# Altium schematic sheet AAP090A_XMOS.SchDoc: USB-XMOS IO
size 538 x 342 mm; Date: Not shown in title block; ApprovedBy: Not shown in title block; CheckedBy: Not shown in title block; Author: Not shown in title block; CompanyName: Not shown in title block; DrawnBy: LDN; Engineer: Not shown in title block; Organization: Not shown in title block; Address1: Not shown in title block; Address2: Not shown in title block; Address3: Not shown in title block; Address4: Not shown in title block; DocumentNumber: 1; Revision: Use project parameter SCH_Rev; SheetNumber: 1; SheetTotal: 6; PageSetup: Record=PageOptions¦CenterHorizontal=True¦CenterVertical=True¦PrintScale=0.77¦XCorrection=1.00¦YCorrection=1.00¦PrintKind=0¦BorderSize=5000000¦LeftOffset=0¦BottomOffset=0¦Orientation=2¦PaperLength=1000¦PaperWidth=1000¦Scale=100¦PaperSource=15¦PrintQuality=600¦MediaType=1¦DitherType=10¦PrintScaleMode=1¦PaperKind=Tabloid (11 x 17")¦PaperIndex=17
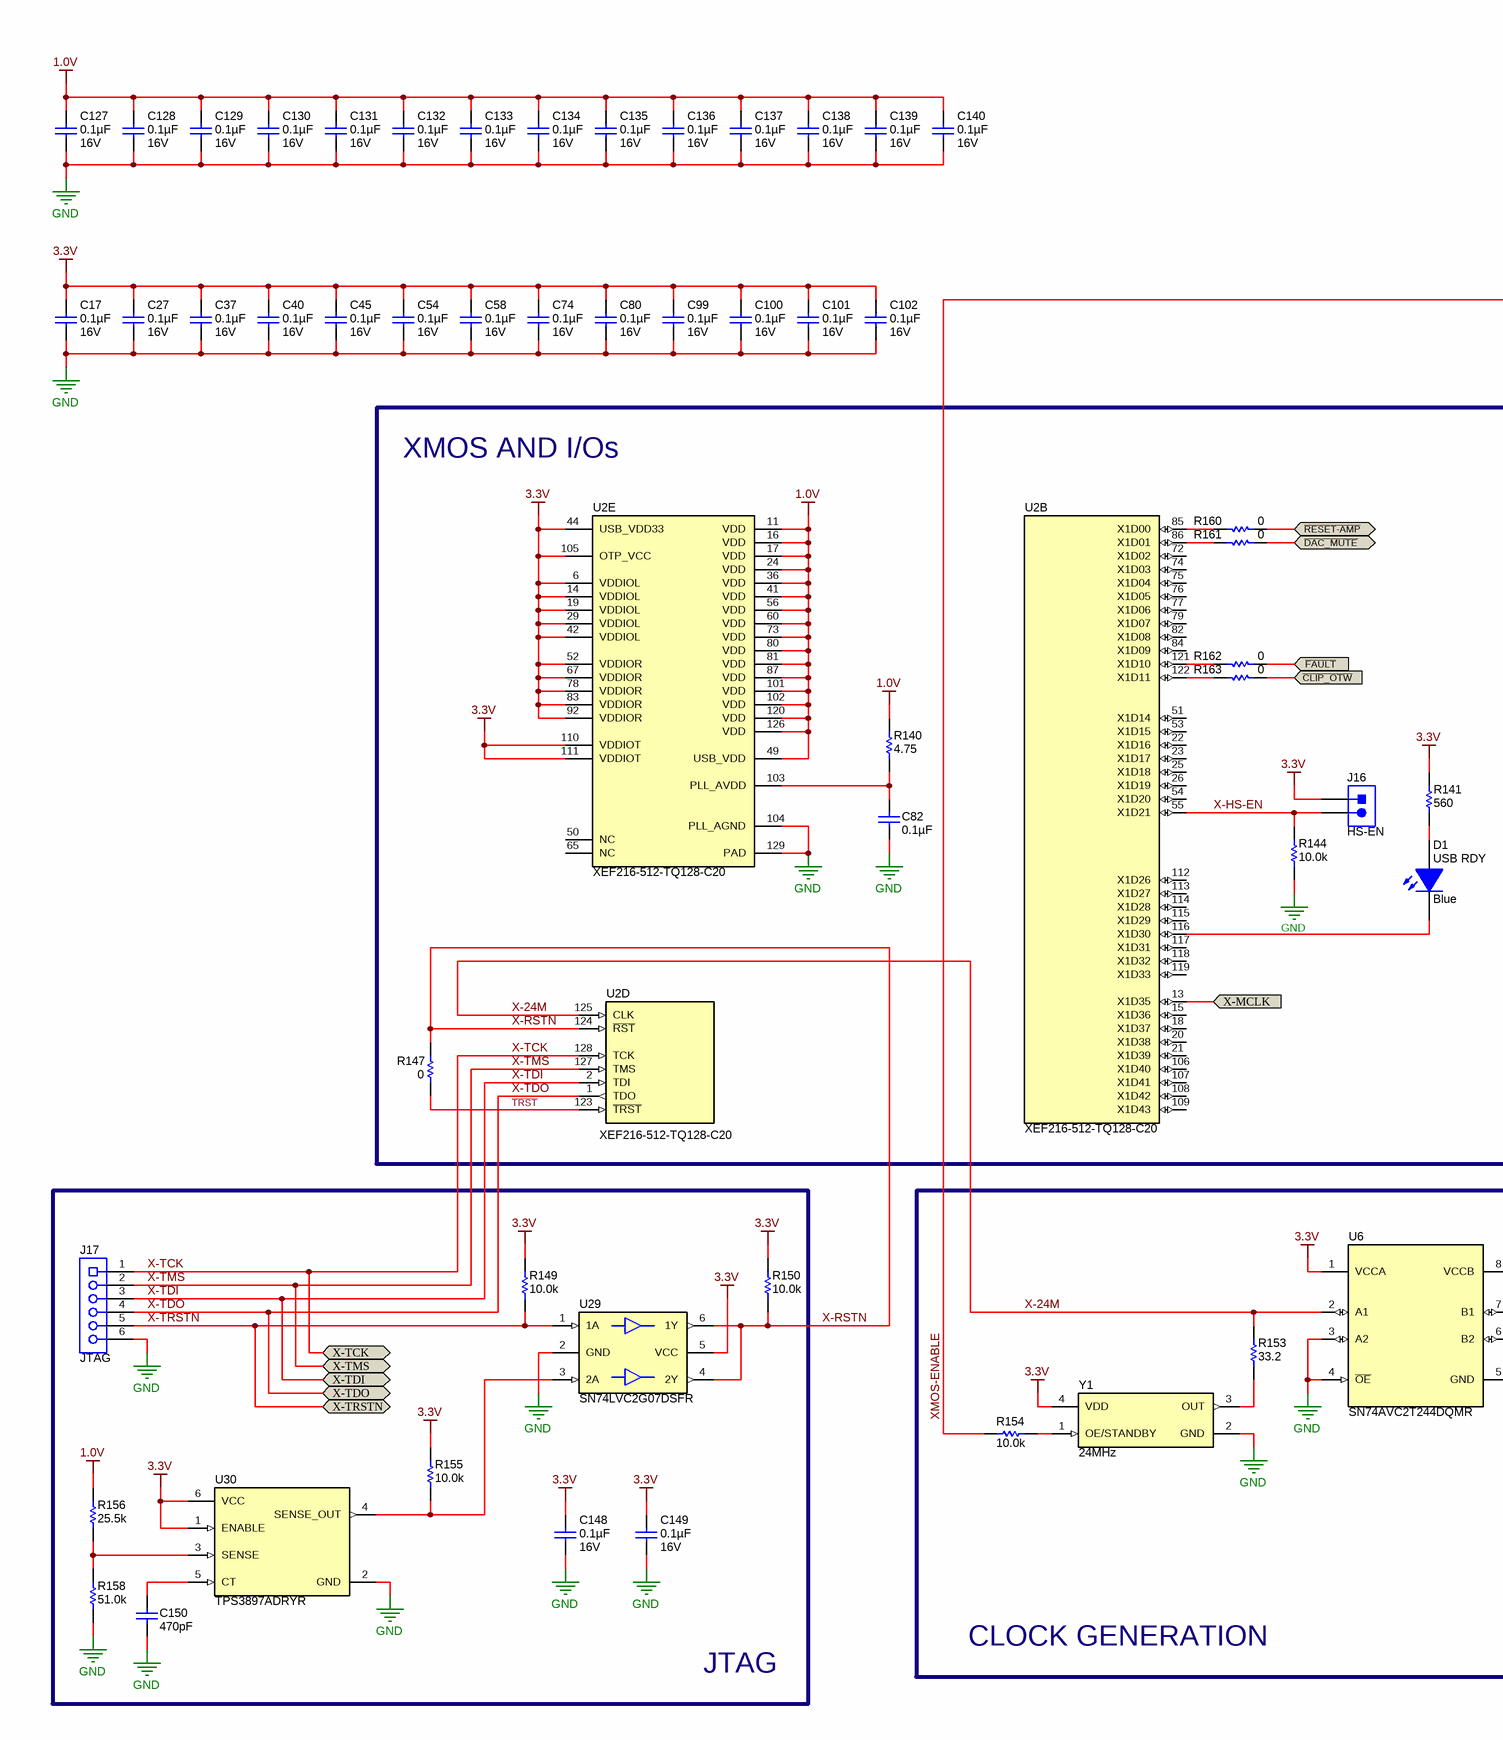
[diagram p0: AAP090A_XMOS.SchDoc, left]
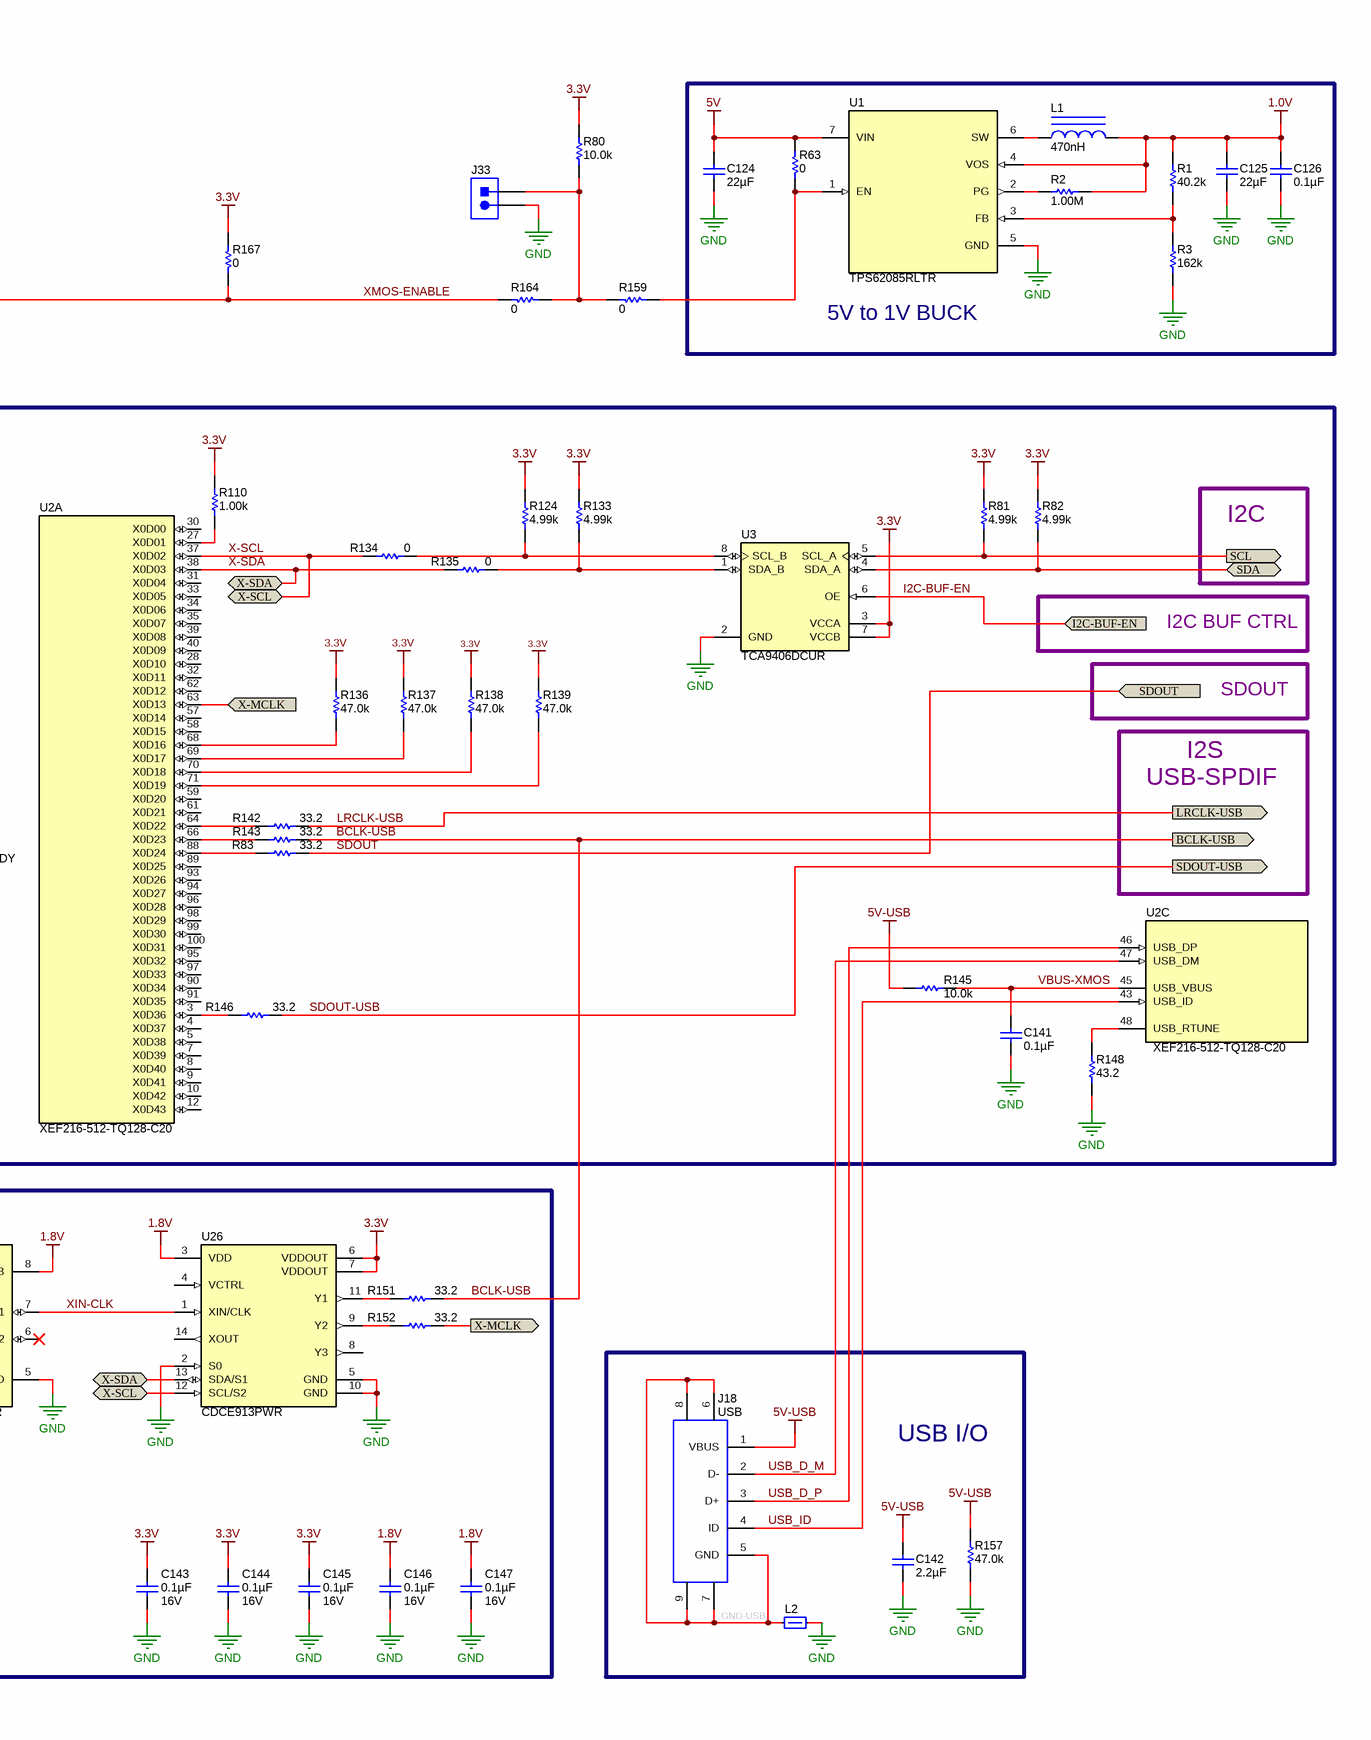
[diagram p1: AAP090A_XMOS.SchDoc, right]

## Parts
(Parts that share a designator on the sheet are numbered #1, #2 ... from top to bottom, then left to right.)
C17  ValueDisplayed: 0.1µF  Value2: 16V  [0402L]  (hidden comment: GRM155R71C104KA88D)
C27  ValueDisplayed: 0.1µF  Value2: 16V  [0402L]  (hidden comment: GRM155R71C104KA88D)
C37  ValueDisplayed: 0.1µF  Value2: 16V  [0402L]  (hidden comment: GRM155R71C104KA88D)
C40  ValueDisplayed: 0.1µF  Value2: 16V  [0402L]  (hidden comment: GRM155R71C104KA88D)
C45  ValueDisplayed: 0.1µF  Value2: 16V  [0402L]  (hidden comment: GRM155R71C104KA88D)
C54  ValueDisplayed: 0.1µF  Value2: 16V  [0402L]  (hidden comment: GRM155R71C104KA88D)
C58  ValueDisplayed: 0.1µF  Value2: 16V  [0402L]  (hidden comment: GRM155R71C104KA88D)
C74  ValueDisplayed: 0.1µF  Value2: 16V  [0402L]  (hidden comment: GRM155R71C104KA88D)
C80  ValueDisplayed: 0.1µF  Value2: 16V  [0402L]  (hidden comment: GRM155R71C104KA88D)
C82  ValueDisplayed: 0.1µF  [0402L]
C99  ValueDisplayed: 0.1µF  Value2: 16V  [0402L]  (hidden comment: GRM155R71C104KA88D)
C100  ValueDisplayed: 0.1µF  Value2: 16V  [0402L]  (hidden comment: GRM155R71C104KA88D)
C101  ValueDisplayed: 0.1µF  Value2: 16V  [0402L]  (hidden comment: GRM155R71C104KA88D)
C102  ValueDisplayed: 0.1µF  Value2: 16V  [0402L]  (hidden comment: GRM155R71C104KA88D)
C124  ValueDisplayed: 22µF  [0805_KTR]  (hidden comment: GRM21BZ71A226ME15L)
C125  ValueDisplayed: 22µF  [0805_KTR]  (hidden comment: GRM21BZ71A226ME15L)
C126  ValueDisplayed: 0.1µF  [0402L]  (hidden comment: GRM155R71C104KA88D)
C127  ValueDisplayed: 0.1µF  Value2: 16V  [0402L]  (hidden comment: GRM155R71C104KA88D)
C128  ValueDisplayed: 0.1µF  Value2: 16V  [0402L]  (hidden comment: GRM155R71C104KA88D)
C129  ValueDisplayed: 0.1µF  Value2: 16V  [0402L]  (hidden comment: GRM155R71C104KA88D)
C130  ValueDisplayed: 0.1µF  Value2: 16V  [0402L]  (hidden comment: GRM155R71C104KA88D)
C131  ValueDisplayed: 0.1µF  Value2: 16V  [0402L]  (hidden comment: GRM155R71C104KA88D)
C132  ValueDisplayed: 0.1µF  Value2: 16V  [0402L]  (hidden comment: GRM155R71C104KA88D)
C133  ValueDisplayed: 0.1µF  Value2: 16V  [0402L]  (hidden comment: GRM155R71C104KA88D)
C134  ValueDisplayed: 0.1µF  Value2: 16V  [0402L]  (hidden comment: GRM155R71C104KA88D)
C135  ValueDisplayed: 0.1µF  Value2: 16V  [0402L]  (hidden comment: GRM155R71C104KA88D)
C136  ValueDisplayed: 0.1µF  Value2: 16V  [0402L]  (hidden comment: GRM155R71C104KA88D)
C137  ValueDisplayed: 0.1µF  Value2: 16V  [0402L]  (hidden comment: GRM155R71C104KA88D)
C138  ValueDisplayed: 0.1µF  Value2: 16V  [0402L]  (hidden comment: GRM155R71C104KA88D)
C139  ValueDisplayed: 0.1µF  Value2: 16V  [0402L]  (hidden comment: GRM155R71C104KA88D)
C140  ValueDisplayed: 0.1µF  Value2: 16V  [0402L]  (hidden comment: GRM155R71C104KA88D)
C141  ValueDisplayed: 0.1µF  [0402L]  (hidden comment: GRM155R71C104KA88D)
C142  ValueDisplayed: 2.2µF  [0603L]  (hidden comment: GRM188R71A225KE15D)
C143  ValueDisplayed: 0.1µF  Value2: 16V  [0402L]  (hidden comment: GRM155R71C104KA88D)
C144  ValueDisplayed: 0.1µF  Value2: 16V  [0402L]  (hidden comment: GRM155R71C104KA88D)
C145  ValueDisplayed: 0.1µF  Value2: 16V  [0402L]  (hidden comment: GRM155R71C104KA88D)
C146  ValueDisplayed: 0.1µF  Value2: 16V  [0402L]  (hidden comment: GRM155R71C104KA88D)
C147  ValueDisplayed: 0.1µF  Value2: 16V  [0402L]  (hidden comment: GRM155R71C104KA88D)
C148  ValueDisplayed: 0.1µF  Value2: 16V  [0402L]  (hidden comment: GRM155R71C104KA88D)
C149  ValueDisplayed: 0.1µF  Value2: 16V  [0402L]  (hidden comment: GRM155R71C104KA88D)
C150  ValueDisplayed: 470pF  [0402L]  (hidden comment: GRM1555C1E471JA01D)
D1  USB RDY  value Blue  [LTST-C170TBKT_Blue]
J16  HS-EN  [Sullins_PBC02SAAN]
J17  JTAG  [SULLINS_LPPB061NGCN-RC]
J18  USB  [CONN_USB_DX4R205JJA]
J33  (no value)  [Sullins_PBC02SAAN]
L1  ValueDisplayed: 470nH  [VLS2012ET]  (hidden comment: VLS2012ET-R47N)
L2  MPZ2012S601A  [0805_KTR]  (value not drawn)
R1  ValueDisplayed: 40.2k  [0402L]  (hidden comment: ERJ-2RKF4022X)
R2  ValueDisplayed: 1.00M  [0603L]  (hidden comment: RC0603FR-071ML)
R3  ValueDisplayed: 162k  [0603L]  (hidden comment: RC0603FR-07162KL)
R63  ValueDisplayed: 0  [0603L]  (hidden comment: DNP)
R80  ValueDisplayed: 10.0k  [0402L]  (hidden comment: ERJ-2RKF1002X)
R81  ValueDisplayed: 4.99k  [0402L]  (hidden comment: RC0402FR-074K99L)
R82  ValueDisplayed: 4.99k  [0402L]  (hidden comment: RC0402FR-074K99L)
R83  ValueDisplayed: 33.2  [0201]  (hidden comment: RC0201FR-0733R2L)
R110  ValueDisplayed: 1.00k  [0402L]  (hidden comment: RC0402FR-071KL)
R124  ValueDisplayed: 4.99k  [0402L]  (hidden comment: RC0402FR-074K99L)
R133  ValueDisplayed: 4.99k  [0402L]  (hidden comment: RC0402FR-074K99L)
R134  ValueDisplayed: 0  [0603L]  (hidden comment: ERJ-3GEY0R00V)
R135  ValueDisplayed: 0  [0603L]  (hidden comment: ERJ-3GEY0R00V)
R136  ValueDisplayed: 47.0k  [0201L]  (hidden comment: RC0201FR-0747KL)
R137  ValueDisplayed: 47.0k  [0201L]  (hidden comment: RC0201FR-0747KL)
R138  ValueDisplayed: 47.0k  [0201L]  (hidden comment: RC0201FR-0747KL)
R139  ValueDisplayed: 47.0k  [0201L]  (hidden comment: RC0201FR-0747KL)
R140  ValueDisplayed: 4.75  [0603L]  (hidden comment: RC0603FR-074R75L)
R141  ValueDisplayed: 560  [0603L]  (hidden comment: RC0603JR-07560RL)
R142  ValueDisplayed: 33.2  [0201]  (hidden comment: RC0201FR-0733R2L)
R143  ValueDisplayed: 33.2  [0201]  (hidden comment: RC0201FR-0733R2L)
R144  ValueDisplayed: 10.0k  [0201L]  (hidden comment: RC0201FR-0710KL)
R145  ValueDisplayed: 10.0k  [0402L]  (hidden comment: ERJ-2RKF1002X)
R146  ValueDisplayed: 33.2  [0201]  (hidden comment: RC0201FR-0733R2L)
R147  ValueDisplayed: 0  [0201L]  (hidden comment: ERJ-1GE0R00C)
R148  ValueDisplayed: 43.2  [0201L]  (hidden comment: RC0201FR-0743R2L)
R149  ValueDisplayed: 10.0k  [0201L]  (hidden comment: RC0201FR-0710KL)
R150  ValueDisplayed: 10.0k  [0201L]  (hidden comment: RC0201FR-0710KL)
R151  ValueDisplayed: 33.2  [0201]  (hidden comment: RC0201FR-0733R2L)
R152  ValueDisplayed: 33.2  [0201]  (hidden comment: RC0201FR-0733R2L)
R153  ValueDisplayed: 33.2  [0201]  (hidden comment: RC0201FR-0733R2L)
R154  ValueDisplayed: 10.0k  [0201L]  (hidden comment: RC0201FR-0710KL)
R155  ValueDisplayed: 10.0k  [0201L]  (hidden comment: RC0201FR-0710KL)
R156  ValueDisplayed: 25.5k  [0201]  (hidden comment: RC0201FR-0725K5L)
R157  ValueDisplayed: 47.0k  [0402L]  (hidden comment: RC0402FR-0747KL)
R158  ValueDisplayed: 51.0k  [0201]  (hidden comment: RC0201FR-0751KL)
R159  ValueDisplayed: 0  [0805_KTR]  (hidden comment: RC0805JR-070RL)
R160  ValueDisplayed: 0  [0201L]  (hidden comment: DNP)
R161  ValueDisplayed: 0  [0201L]  (hidden comment: DNP)
R162  ValueDisplayed: 0  [0201L]  (hidden comment: DNP)
R163  ValueDisplayed: 0  [0201L]  (hidden comment: DNP)
R164  ValueDisplayed: 0  [0805_KTR]  (hidden comment: RC0805JR-070RL)
R167  ValueDisplayed: 0  [0603L]  (hidden comment: DNP)
U1  TPS62085RLTR  [RLT0007A]
U2#1  XEF216-512-TQ128-C20  [TQFP-128]  (part A of 5)
U2#2  XEF216-512-TQ128-C20  [TQFP-128]  (parts B,C,D,E of 5)
U3  TCA9406DCUR  [DCU0008A_N]
U6  SN74AVC2T244DQMR  [DQM0008A]
U26  CDCE913PWR  [PW0014A_N]
U29  SN74LVC2G07DSFR  [DSF0006A]
U30  TPS3897ADRYR  [DRY0006A]
Y1  Frequency: 24MHz  [Abracon_ASTMLPA]  (hidden comment: ASTMLPA-24.000MHZ-EJ-E-T)

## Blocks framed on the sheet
5V to 1V BUCK: C124-C126 L1 R1-R3 R63 U1
XMOS AND I/Os: C82 C141 D1 J16 R81-R83 R110 R124 R133-R148 R160-R163 U2#1 U2#2 U3
JTAG: C148-C150 J17 R149 R150 R155 R156 R158 U29 U30
CLOCK GENERATION: C143-C147 R151-R154 U6 U26 Y1
USB I/O: C142 J18 L2 R157

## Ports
BCLK-USB (out), I2C-BUF-EN (in), LRCLK-USB (out), SCL (out), SDA (bidir), SDOUT (in), SDOUT-USB (out), X-MCLK (in), X-MCLK (out), X-SCL (bidir), X-SDA (bidir), X-TCK (bidir), X-TDI (bidir), X-TDO (bidir), X-TMS (bidir), X-TRSTN (bidir), ~{CLIP_OTW} (in), ~{DAC_MUTE} (bidir), ~{FAULT} (in), ~{RESET-AMP} (bidir)

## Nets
1.0V: C125.1 C126.1 C127.2 C128.2 C129.2 C130.2 C131.2 C132.2 C133.2 C134.2 C135.2 C136.2 C137.2 C138.2 C139.2 C140.2 L1.2 R1.2 R2.2 R140.1 R156.1 U1.4(VOS) U2#2.11(VDD) U2#2.16(VDD) U2#2.17(VDD) U2#2.24(VDD) U2#2.36(VDD) U2#2.41(VDD) U2#2.49(USB_VDD) U2#2.56(VDD) U2#2.60(VDD) U2#2.73(VDD) U2#2.80(VDD) U2#2.81(VDD) U2#2.87(VDD) U2#2.101(VDD) U2#2.102(VDD) U2#2.120(VDD) U2#2.126(VDD)
1.8V: C146.2 C147.2 U6.8(VCCB) U26.3(VDD)
3.3V: C17.2 C27.2 C37.2 C40.2 C45.2 C54.2 C58.2 C74.2 C80.2 C99.2 C100.2 C101.2 C102.2 C143.2 C144.2 C145.2 C148.2 C149.2 J16.1 R80.1 R81.2 R82.2 R110.1 R124.2 R133.2 R136.2 R137.2 R138.2 R139.2 R141.1 R149.1 R150.1 R155.1 R167.1 U2#2.6(VDDIOL) U2#2.14(VDDIOL) U2#2.19(VDDIOL) U2#2.29(VDDIOL) U2#2.42(VDDIOL) U2#2.44(USB_VDD33) U2#2.52(VDDIOR) U2#2.67(VDDIOR) U2#2.78(VDDIOR) U2#2.83(VDDIOR) U2#2.92(VDDIOR) U2#2.105(OTP_VCC) U2#2.110(VDDIOT) U2#2.111(VDDIOT) U3.3(VCCA) U3.7(VCCB) U6.1(VCCA) U26.6(VDDOUT) U26.7(VDDOUT) U29.5(VCC) U30.1(ENABLE) U30.6(VCC) Y1.4(VDD)
5V: C124.1 R63.1 U1.7(VIN)
5V-USB: C142.2 J18.1(VBUS) R145.2 R157.2
GND: C17.1 C27.1 C37.1 C40.1 C45.1 C54.1 C58.1 C74.1 C80.1 C82.2 C99.1 C100.1 C101.1 C102.1 C124.2 C125.2 C126.2 C127.1 C128.1 C129.1 C130.1 C131.1 C132.1 C133.1 C134.1 C135.1 C136.1 C137.1 C138.1 C139.1 C140.1 C141.2 C142.1 C143.1 C144.1 C145.1 C146.1 C147.1 C148.1 C149.1 C150.1 J17.6 J33.2 L2.2 R3.1 R144.1 R148.1 R157.1 R158.2 U1.5(GND) U2#2.104(PLL_AGND) U2#2.129(PAD) U3.2(GND) U6.3(A2) U6.4(~{OE}) U6.5(GND) U26.2(S0) U26.5(GND) U26.10(GND) U29.2(GND) U30.2(GND) Y1.2(GND)
~{CLIP_OTW}: R163.1 ; port ~{CLIP_OTW}
~{DAC_MUTE}: R161.1 ; port ~{DAC_MUTE}
~{FAULT}: R162.1 ; port ~{FAULT}
~{RESET-AMP}: R160.1 ; port ~{RESET-AMP}
~{TRST}: R147.1 U2#2.123(~{TRST})
BCLK-USB: R143.1 R151.1 ; port BCLK-USB
GND-USB: J18.5(GND) J18.6 J18.7 J18.8 J18.9 L2.1
I2C-BUF-EN: U3.6(OE) ; port I2C-BUF-EN
LRCLK-USB: R142.1 ; port LRCLK-USB
SCL: R81.1 U3.5(SCL_A) ; port SCL
SDA: R82.1 U3.4(SDA_A) ; port SDA
SDOUT: R83.1 ; port SDOUT
SDOUT-USB: R146.1 ; port SDOUT-USB
USB_D_M: J18.2(D-) U2#2.47(USB_DM)
USB_D_P: J18.3(D+) U2#2.46(USB_DP)
USB_ID: J18.4(ID) U2#2.43(USB_ID)
VBUS-XMOS: C141.1 R145.1 U2#2.45(USB_VBUS)
X-24M: R153.2 U2#2.125(CLK) U6.2(A1)
X-HS-EN: J16.2 R144.2 U2#2.55(X1D21)
X-MCLK: R152.1 U2#1.63(X0D13) U2#2.13(X1D35) ; port X-MCLK
X-RSTN: R147.2 R150.2 U2#2.124(~{RST}) U29.4(2Y) U29.6(1Y)
X-SCL: R134.1 U2#1.37(X0D02) U26.12(SCL/S2) ; port X-SCL
X-SDA: R135.1 U2#1.38(X0D03) U26.13(SDA/S1) ; port X-SDA
X-TCK: J17.1 U2#2.128(TCK) ; port X-TCK
X-TDI: J17.3 U2#2.2(TDI) ; port X-TDI
X-TDO: J17.4 U2#2.1(TDO) ; port X-TDO
X-TMS: J17.2 U2#2.127(TMS) ; port X-TMS
X-TRSTN: J17.5 R149.2 U29.1(1A) ; port X-TRSTN
XIN-CLK: U6.7(B1) U26.1(XIN/CLK)
XMOS-ENABLE: R154.1 R164.2 R167.2
NetC82_1: C82.1 R140.2 U2#2.103(PLL_AVDD)
NetC150_2: C150.2 U30.5(CT)
NetD1_1: D1.1(A) R141.2
NetD1_2: D1.2(K) U2#2.116(X1D30)
NetJ33_1: J33.1 R80.2 R159.2 R164.1
NetL1_1: L1.1 U1.6(SW)
NetR1_1: R1.1 R3.2 U1.3(FB)
NetR2_1: R2.1 U1.2(PG)
NetR63_2: R63.2 R159.1 U1.1(EN)
NetR83_2: R83.2 U2#1.88(X0D24)
NetR110_2: R110.2 U2#1.27(X0D01)
NetR124_1: R124.1 R134.2 U3.8(SCL_B)
NetR133_1: R133.1 R135.2 U3.1(SDA_B)
NetR136_1: R136.1 U2#1.68(X0D16)
NetR137_1: R137.1 U2#1.69(X0D17)
NetR138_1: R138.1 U2#1.70(X0D18)
NetR139_1: R139.1 U2#1.71(X0D19)
NetR142_2: R142.2 U2#1.64(X0D22)
NetR143_2: R143.2 U2#1.66(X0D23)
NetR146_2: R146.2 U2#1.3(X0D36)
NetR148_2: R148.2 U2#2.48(USB_RTUNE)
NetR151_2: R151.2 U26.11(Y1)
NetR152_2: R152.2 U26.9(Y2)
NetR153_1: R153.1 Y1.3(OUT)
NetR154_2: R154.2 Y1.1(OE/STANDBY)
NetR155_2: R155.2 U29.3(2A) U30.4(SENSE_OUT)
NetR156_2: R156.2 R158.1 U30.3(SENSE)
NetR160_2: R160.2 U2#2.85(X1D00)
NetR161_2: R161.2 U2#2.86(X1D01)
NetR162_2: R162.2 U2#2.121(X1D10)
NetR163_2: R163.2 U2#2.122(X1D11)

Not connected (* = marked no-connect by the designer): U2#1 4(X0D37) 5(X0D38) 7(X0D39) 8(X0D40) 9(X0D41) 10(X0D42) 12(X0D43) 28(X0D10) 30(X0D00) 31(X0D04) 32(X0D11) 33(X0D05) 34(X0D06) 35(X0D07) 39(X0D08) 40(X0D09) 57(X0D14) 58(X0D15) 59(X0D20) 61(X0D21) 62(X0D12) 89(X0D25) 90(X0D34) 91(X0D35) 93(X0D26) 94(X0D27) 95(X0D32) 96(X0D28) 97(X0D33) 98(X0D29) 99(X0D30) 100(X0D31); U2#2 15(X1D36) 18(X1D37) 20(X1D38) 21(X1D39) 22(X1D16) 23(X1D17) 25(X1D18) 26(X1D19) 50(NC) 51(X1D14) 53(X1D15) 54(X1D20) 65(NC) 72(X1D02) 74(X1D03) 75(X1D04) 76(X1D05) 77(X1D06) 79(X1D07) 82(X1D08) 84(X1D09) 106(X1D40) 107(X1D41) 108(X1D42) 109(X1D43) 112(X1D26) 113(X1D27) 114(X1D28) 115(X1D29) 117(X1D31) 118(X1D32) 119(X1D33); U6 6(B2)*; U26 4(VCTRL) 8(Y3) 14(XOUT)

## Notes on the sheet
- I2C
- I2C BUF CTRL
- SDOUT
- USB-SPDIF
- I2S

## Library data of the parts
C17 C27 C37 C40 C45 C54 C58 C74 C80 C99-C102 C127-C140 C143-C149 = GRM155R71C104KA88D: CAP, CERM, 0.1uF, 16V, +/-10%, X7R, 0402; Manufacturer: MuRata; Polarized: N; CompType: Capacitor; U/M: EA; Cap_F: 0.0000001; Tolerance_%: 10; Value1: Unknown; VDC_V: 16; TaMin_C: -55; TaMax_C: 125; Cap_Case: 0402
C82 C126 C141 = GRM155R71C104KA88D: CAP, CERM, 0.1 µF, 16 V, +/- 10%, X7R, 0402; Manufacturer: MuRata; Polarized: N; CompType: Capacitor; Value: 0.1uF; U/M: EA; Cap_F: 0.0000001; Tolerance_%: 10; Value1: Unknown; VDC_V: 16; Value2: 16V; TaMin_C: -55; TaMax_C: 125; Cap_Case: 0402; AEC Category: Q200
C124 C125 = GRM21BZ71A226ME15L: CAP, CERM, 22 µF, 10 V, +/- 20%, X7R, 0805; Manufacturer: MuRata; Polarized: N; CompType: Capacitor; Value: 22uF; U/M: EA; Cap_F: 0.000022; Tolerance_%: 20; Value1: Unknown; VDC_V: 10; Value2: 10V; TaMin_C: -55; TaMax_C: 125; Cap_Case: 0805; AEC Category: Q200
C142 = GRM188R71A225KE15D: CAP, CERM, 2.2 µF, 10 V, +/- 10%, X7R, 0603; Manufacturer: MuRata; Polarized: N; CompType: Capacitor; Value: 2.2uF; U/M: EA; Cap_F: 0.0000022; Tolerance_%: 10; ESR_ohm: 0.009; Value1: 0.009 ohm; Value2: 10V; TaMin_C: -55; TaMax_C: 125; Cap_Case: 0603; SizeArea_mm2: 1.28; SizeAreaWB_mm2: 4.68; SizeX_mm: 1.6; SizeY_mm: 0.8; SizeZ_mm: 1; AEC Category: Q200
C150 = GRM1555C1E471JA01D: CAP, CERM, 470 pF, 25 V, +/- 5%, C0G/NP0, 0402; Manufacturer: MuRata; Polarized: N; CompType: Capacitor; Value: 470pF; U/M: EA; Cap_F: 0.00000000047; Tolerance_%: 5; Value1: Unknown; VDC_V: 25; Value2: 25V; TaMin_C: -55; TaMax_C: 125; Cap_Case: 0402; SizeArea_mm2: 0.5; SizeAreaWB_mm2: 3; SizeX_mm: 1; SizeZ_mm: 0.6; AEC Category: Q200
D1 = LTST-C170TBKT: LED, Blue, SMD; Manufacturer: Lite-On; Type: AlInGaP; Vf_V: 3.3; Value2: 3.3V; Io_A: 0.02; Value1: W; U/M: EA
J16 J33 = PBC02SAAN: Header, 100mil, 2x1, Gold, TH; Manufacturer: Sullins Connector Solutions; SymbolCreator: a0412235; Pitch_mm: 2.54; Gender: Male; Shrouded: N; Row_Count: 1; Current_A: 3; Voltage_V: 1800; Cert_UL: Y
J17 = LPPB061NGCN-RC: Receptacle, 50mil, 6x1, Gold, R/A, TH; Manufacturer: Sullins Connector Solutions; SymbolCreator: a0411947
J18 = CMP-0074926-1: Connector, Receptacle, Micro-USB Type AB, R/A, Bottom Mount SMT; Manufacturer: JAE Electronics; PartNumber: DX4R205JJAR1800; CNHeader: False; Green_Lifecycle: Not Set; Gender: Female; Green_REACh: Incomplete; CT: True
L1 = VLS2012ET-R47N: Inductor, Shielded Drum Core, Ferrite, 470 nH, 2 A, 0.059 ohm, SMD; Manufacturer: TDK; Value: 470nH; Ind_H: 470.0E-9; Imax_A: 2; Irms: 2A @ 40C rise; Isat: 2.25A @ 30% inductance drop; DCR_ohm: 0.059; Value2: 2A; AEC Category: Q200
L2 = MPZ2012S601A: Ferrite Bead, 600 ohm @ 100MHz, 2A, 0805; Manufacturer: TDK; Value: 600 ohm; Imax_A: 2; DCR_ohm: 0.1; Value1: 0.1 ohm; ZTyp@100MHz_Ohm: 600
R1 = ERJ-2RKF4022X: RES, 40.2 k, 1%, 0.1 W, AEC-Q200 Grade 0, 0402; Manufacturer: Panasonic; CompType: Resistor; Value: 40.2k; Res_ohm: 40200; Value_Code: 40k2; Tolerance_%: 1; Power_W: 0.1; Value2: 0.1W; VDC_V: 50; TempCo: 100 ppm/C; EIA_Code: E96; U/M: EA; AEC Category: Q200; AEC Qualified: Y; AEC Grade: 0; SizeArea_mm2: 0.5; SizeZ_mm: 0.6; Green_Lifecycle: Active; Green_REACh: Passed
R2 = RC0603FR-071ML: RES, 1.00 M, 1%, 0.1 W, 0603; Manufacturer: Yageo America; CompType: Resistor; Value: 1.00Meg; Res_ohm: 1000000; Value_Code: 1M00; Tolerance_%: 1; Power_W: 0.1; Value2: 0.1W; VDC_V: 150; TempCo: 200 ppm/C; EIA_Code: E96; U/M: EA; AEC Category: Q200; SizeArea_mm2: 1.28; SizeX_mm: 1.6; SizeY_mm: 0.8; Green_Lifecycle: Active; Green_REACh: Passed
R3 = RC0603FR-07162KL: RES, 162 k, 1%, 0.1 W, 0603; Manufacturer: Yageo America; CompType: Resistor; Value: 162k; Res_ohm: 162000; Tolerance_%: 1; Power_W: 0.1; Value2: 0.1W; VDC_V: 150; TempCo: 200 ppm/C; EIA_Code: E96; U/M: EA; AEC Category: Q200; SizeArea_mm2: 1.28; SizeX_mm: 1.6; SizeY_mm: 0.8; Green_Lifecycle: Active; Green_REACh: Passed
R63 R134 R135 R167 = ERJ-3GEY0R00V: RES, 0, 5%, 0.1 W, 0603; Manufacturer: Panasonic; CompType: Resistor; Value: 0; Value_Code: 0000; Tolerance_%: 5; Power_W: 0.1; Value2: 0.1W; VDC_V: 50; TempCo: 600 ppm/C; EIA_Code: E24; U/M: EA; AEC Category: Q200; SizeArea_mm2: 1.28; SizeX_mm: 1.6; SizeY_mm: 0.8; SizeZ_mm: 1; Green_Lifecycle: Active; Green_REACh: Passed
R80 R145 = ERJ-2RKF1002X: RES, 10.0 k, 1%, 0.1 W, 0402; Manufacturer: Panasonic; CompType: Resistor; Value: 10.0k; Res_ohm: 10000; Value_Code: 10k0; Tolerance_%: 1; Power_W: 0.1; Value2: 0.1W; VDC_V: 50; TempCo: 100 ppm/C; EIA_Code: E96; U/M: EA; AEC Category: Q200; SizeArea_mm2: 0.5; SizeZ_mm: 0.6
R81 R82 R124 R133 = RC0402FR-074K99L: RES, 4.99 k, 1%, 0.063 W, 0402; Manufacturer: Yageo America; CompType: Resistor; Value: 4.99k; Res_ohm: 4990; Value_Code: 4k99; Tolerance_%: 1; Power_W: 0.063; Value2: 0.063W; VDC_V: 50; TempCo: 100 ppm/C; EIA_Code: E96; U/M: EA; AEC Category: Q200; AEC Qualified: N; SizeArea_mm2: 0.5; SizeZ_mm: 0.6; Green_Lifecycle: Active; Green_REACh: Passed
R83 R142 R143 R146 R151-R153 = RC0201FR-0733R2L: RES, 33.2, 1%, 0.05 W, 0201; Manufacturer: Yageo America; CompType: Resistor; Value: 33.2; Value_Code: 33R2; Tolerance_%: 1; Power_W: 0.05; Value2: 0.05W; VDC_V: 25; TempCo: 200 ppm/C; EIA_Code: E96; U/M: EA; SizeArea_mm2: 0.18; SizeX_mm: 0.6; SizeY_mm: 0.3; SizeZ_mm: 0.26; AEC Category: Q200; AEC Qualified: N
R110 = RC0402FR-071KL: RES, 1.00 k, 1%, 0.0625 W, 0402; Manufacturer: Yageo America; CompType: Resistor; Value: 1.00k; Res_ohm: 1000; Value_Code: 1k00; Tolerance_%: 1; Power_W: 0.0625; VDC_V: 50; TempCo: 100 ppm/C; EIA_Code: E96; U/M: EA; AEC Category: Q200; AEC Qualified: N; SizeArea_mm2: 0.5; SizeZ_mm: 0.6; Green_Lifecycle: Active; Green_REACh: Passed
R136-R139 = RC0201FR-0747KL: RES, 47.0 k, 1%, 0.05 W, 0201; Manufacturer: Yageo America; CompType: Resistor; Value: 47.0k; Res_ohm: 47000; Value_Code: 47k0; Tolerance_%: 1; Power_W: 0.05; Value2: 0.05W; VDC_V: 25; TempCo: 200 ppm/C; U/M: EA; AEC Category: Q200; AEC Qualified: N; SizeArea_mm2: 0.18; SizeX_mm: 0.6; SizeY_mm: 0.3; SizeZ_mm: 0.26
R140 = RC0603FR-074R75L: RES, 4.75, 1%, 0.1 W, 0603; Manufacturer: Yageo America; CompType: Resistor; Value: 4.75; Value_Code: 4R75; Tolerance_%: 1; Power_W: 0.1; Value2: 0.1W; VDC_V: 150; TempCo: 200 ppm/C; EIA_Code: E96; U/M: EA; AEC Category: Q200; SizeArea_mm2: 1.28; SizeX_mm: 1.6; SizeY_mm: 0.8
R141 = RC0603JR-07560RL: RES, 560, 5%, 0.1 W, 0603; Manufacturer: Yageo America; CompType: Resistor; Value: 560; Value_Code: 560R; Tolerance_%: 5; Power_W: 0.1; Value2: 0.1W; VDC_V: 50; TempCo: 100 ppm/C; EIA_Code: E24; U/M: EA; AEC Category: Q200; SizeArea_mm2: 1.28; SizeX_mm: 1.6; SizeY_mm: 0.8; SizeZ_mm: 1
R144 = RC0201FR-0710KL: RES, 10.0 k, 1%, 0.05 W, 0201; Manufacturer: Yageo America; CompType: Resistor; Value: 10.0k; Res_ohm: 10000; Value_Code: 10k0; Tolerance_%: 1; Power_W: 0.05; Value2: 0.05W; VDC_V: 25; TempCo: 200 ppm/C; EIA_Code: E96; U/M: EA; AEC Category: Q200; AEC Qualified: N; SizeArea_mm2: 0.18; SizeX_mm: 0.6; SizeY_mm: 0.3; SizeZ_mm: 0.26
R147 R160-R163 = ERJ-1GE0R00C: RES, 0, 5%, 0.05 W, 0201; Manufacturer: Panasonic; CompType: Resistor; Value: 0; Value_Code: 0000; Tolerance_%: 5; Power_W: 0.05; Value2: 0.05W; VDC_V: 15; TempCo: 600 ppm/C; EIA_Code: E24; U/M: EA; AEC Category: Q200; SizeArea_mm2: 0.18; SizeX_mm: 0.6; SizeY_mm: 0.3; SizeZ_mm: 0.26
R148 = RC0201FR-0743R2L: RES, 43.2, 1%, 0.05 W, 0201; Manufacturer: Yageo America; CompType: Resistor; Value: 43.2; Value_Code: 43R2; Tolerance_%: 1; Power_W: 0.05; Value2: 0.05W; VDC_V: 25; TempCo: 200 ppm/C; EIA_Code: E96; U/M: EA; AEC Category: Q200; AEC Qualified: N; SizeArea_mm2: 0.18; SizeX_mm: 0.6; SizeY_mm: 0.3; SizeZ_mm: 0.26
R149 R150 R154 R155 = RC0201FR-0710KL: RES, 10.0 k, 1%, 0.05 W, 0201; Manufacturer: Yageo America; CompType: Resistor; Value: 10.0k; Res_ohm: 10000; Value_Code: 10k0; Tolerance_%: 1; Power_W: 0.05; Value2: 0.05W; VDC_V: 25; TempCo: 200 ppm/C; SizeArea_mm2: 0.18; SizeX_mm: 0.6; SizeY_mm: 0.3; SizeZ_mm: 0.26; EIA_Code: E96; U/M: EA; AEC Category: Q200; AEC Qualified: N
R156 = RC0201FR-0725K5L: RES, 25.5 k, 1%, 0.05 W, 0201; Manufacturer: Yageo America; CompType: Resistor; Value: 25.5k; Res_ohm: 25500; Value_Code: 25k5; Tolerance_%: 1; Power_W: 0.05; Value2: 0.05W; VDC_V: 25; TempCo: 200 ppm/C; SizeArea_mm2: 0.18; SizeX_mm: 0.6; SizeY_mm: 0.3; SizeZ_mm: 0.26; EIA_Code: E96; U/M: EA; AEC Category: Q200; AEC Qualified: N
R157 = RC0402FR-0747KL: RES, 47.0 k, 1%, 0.0625 W, 0402; Manufacturer: Yageo America; CompType: Resistor; Value: 47.0k; Res_ohm: 47000; Value_Code: 47k0; Tolerance_%: 1; Power_W: 0.0625; VDC_V: 50; TempCo: 100 ppm/C; U/M: EA; AEC Category: Q200; AEC Qualified: N; SizeArea_mm2: 0.5; SizeZ_mm: 0.6
R158 = RC0201FR-0751KL: RES, 51.0 k, 1%, 0.05 W, 0201; Manufacturer: Yageo America; CompType: Resistor; Value: 51.0k; Res_ohm: 51000; Value_Code: 51k0; Tolerance_%: 1; Power_W: 0.05; Value2: 0.05W; VDC_V: 25; TempCo: 200 ppm/C; SizeArea_mm2: 0.18; SizeX_mm: 0.6; SizeY_mm: 0.3; SizeZ_mm: 0.26; U/M: EA; AEC Category: Q200; AEC Qualified: N
R159 R164 = RC0805JR-070RL: RES, 0, 5%, 0.125 W, 0805; Manufacturer: Yageo America; CompType: Resistor; Value: 0; Value_Code: 0000; Tolerance_%: 5; Power_W: 0.125; Value2: 0.125W; VDC_V: 150; TempCo: 200 ppm/C; EIA_Code: E24; U/M: EA; AEC Category: Q200; SizeArea_mm2: 2.5; SizeX_mm: 2; SizeY_mm: 1.25; SizeZ_mm: 1.45; Green_Lifecycle: Active; Green_REACh: Passed
U1 = TPS62085RLTR: 3-A Step-Down Converter with Hiccup Short Circuit Protection in 2x2 QFN Package, RLT0007A; Alternate PartNumber: TPS62085RLTT; Manufacturer: Texas Instruments; SymbolCreator: a0411947; CompType: IC; U/M: EA
U2#1 U2#2 = CMP-0004936-1: IC MCU 512KB RAM, 128TQFP; Manufacturer: XMOS semiconductor
U3 = TCA9406DCUR: TCA9406 Dual Bidirectional 1-MHz I2C-BUS and SMBus Voltage Level-Translator, 1.65 to 3.6 V, -40 to 85 degC, 8-pin US8 (DCU), Green (RoHS & no Sb/Br); Manufacturer: Texas Instruments; Alternate PartNumber: Equivalent; SubFamily: I2C Special Function; No. of Outputs: 2; VCC(Min)(V): -0.5; VCC(Max)(V): 4.6; Max Frequency(kHz): 1000; Function: I2C Voltage Level Translator; Enable Pin: Yes; Rating: Catalog
U6 = SN74AVC2T244DQMR: 2-BIT UNDIRECTIONAL VOLTAGE-LEVEL TRANSLATOR, DQM0008A (X2SON-8); Manufacturer: Texas Instruments; SymbolCreator: a0411947; SizeArea_mm2: 2.16; SizeAreaWB_mm2: 6.16; SizeX_mm: 1.2; SizeY_mm: 1.8; SizeZ_mm: 0.4; CompType: IC; U/M: EA
U26 = CDCE913PWR: Programmable 1-PLL VCXO Clock Synthesizer With 1.8-V, 2.5-V, and 3.3-V Outputs, PW0014A (TSSOP-14); Manufacturer: Texas Instruments; SymbolCreator: a0411947; SizeArea_mm2: 32; SizeAreaWB_mm2: 58.8; SizeX_mm: 6.4; SizeY_mm: 5; SizeZ_mm: 1.2; CompType: IC; U/M: EA
U29 = SN74LVC2G07DSFR: DUAL BUFFER/DRIVER WITH OPEN DRAIN OUTPUTS, DSF0006A; Manufacturer: Texas Instruments; SymbolCreator: x0208326; CompType: IC; U/M: EA
U30 = TPS3897ADRYR: Single-Channel, Adjustable Supervisory Circuit in Ultra-Small Package, DRY0006A (USON-6); Alternate PartNumber: TPS3897ADRYT; Manufacturer: Texas Instruments; SymbolCreator: a0411947; SizeArea_mm2: 1.45; SizeAreaWB_mm2: 4.9; SizeX_mm: 1; SizeZ_mm: 0.6; CompType: IC; U/M: EA
Y1 = ASTMLPA-24.000MHZ-EJ-E-T: OSC, 24 MHz, 2.25 - 3.63 V, SMD; Manufacturer: Abracon Corporation; SymbolCreator: x0208326; CompType: Oscillator; U/M: EA; TaMin_C: -20; TaMax_C: 70; Frequency Stability: ±20ppm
